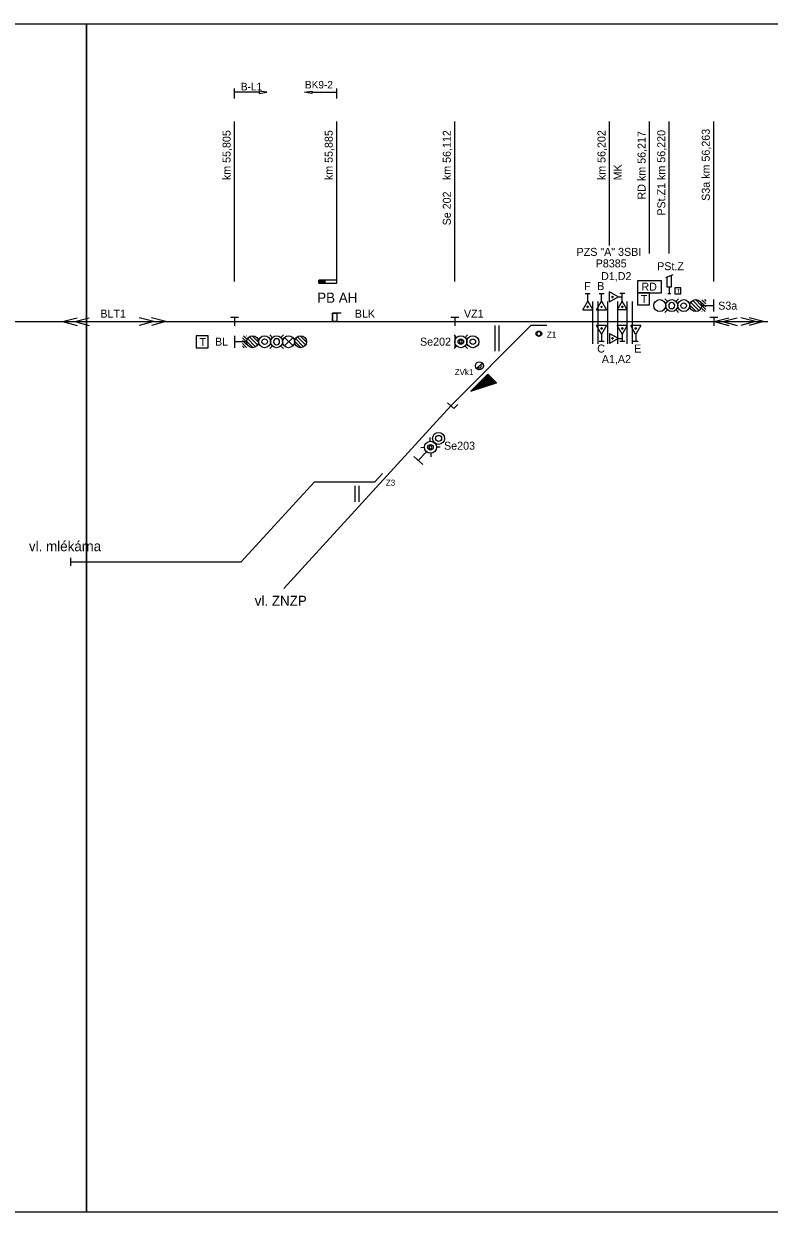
# Model space of a CAD drawing. Extents: x -1146 to 534, y 4 to 301.
# Drawn here: x -951.7 to -765.5, y 4.4 to 301.4 of the extents above; entities that cross this region are included whole.
import ezdxf

# ---------------------------------------------------------------- set-up
doc = ezdxf.new("R2010")
doc.units = 0
for name, color, linetype in [('_Nové', 7, 'Continuous'), ('formát tisku', 7, 'Continuous'), ('koleje', 7, 'Continuous'), ('návěstidla', 7, 'Continuous'), ('popisy', 7, 'Continuous'), ('čd', 7, 'Continuous')]:
    doc.layers.add(name, color=color, linetype=linetype)

# ---------------------------------------------------------------- blocks, each defined once
blk = doc.blocks.new('_X11')
for p, q in [((-0.5, 5.16), (0.34, 6)), ((-0.5, 5.33), (0.17, 6)), ((-0.5, 5.51), (-0.01, 6)), ((-0.5, 5.69), (-0.19, 6)), ((-0.5, 5.86), (-0.36, 6)), ((-0.5, 4.98), (0.5, 5.98)), ((-0.5, 4.8), (0.5, 5.8)), ((-0.5, 4.63), (0.5, 5.63)), ((-0.5, 4.45), (0.5, 5.45)), ((-0.5, 4.27), (0.5, 5.27)), ((-0.5, 4.1), (0.5, 5.1)), ((-0.42, 4), (0.5, 4.92)), ((-0.24, 4), (0.5, 4.74)), ((-0.07, 4), (0.5, 4.57)), ((0.11, 4), (0.5, 4.39)), ((0.29, 4), (0.5, 4.21)), ((0.46, 4), (0.5, 4.04))]:
    blk.add_line(p, q)
blk = doc.blocks.new('PZ15')
for p, q in [((0.5, 6), (-0.5, 6)), ((-0.5, 6), (-0.5, 0)), ((0.5, 0), (0.5, 6)), ((-0.5, 0), (0.5, 0))]:
    blk.add_line(p, q)
blk.add_lwpolyline([(0.5, 6), (0.5, 4), (-0.5, 4), (-0.5, 6)], close=True)
blk.add_lwpolyline([(-0.5, 6), (0.5, 6), (0.5, 4), (-0.5, 4), (-0.5, 6)])
blk.add_blockref('_X11', (0, 0))
blk = doc.blocks.new('O9')
for p, q in [((-1.5, 3), (-1.5, 0)), ((1.5, 3), (-1.5, 3)), ((1.5, 0), (1.5, 3)), ((-1.5, 0), (1.5, 0))]:
    blk.add_line(p, q)
blk.add_text('T', height=2).set_placement((-0.68, 0.41))
blk = doc.blocks.new('SB1')
for p, q in [((0, 1.08), (-1, 1.08)), ((1, 1.08), (0, 1.08)), ((0, 1.08), (0, -1.08))]:
    blk.add_line(p, q)
blk = doc.blocks.new('NS16')
for p, q in [((-1.499, 0.6437), (-1.1298, 1.0129)), ((-1.4356, 0), (-0.4227, 1.0129)), ((-0.7285, 0), (0.2844, 1.0129)), ((-0.0214, 0), (0.9915, 1.0129)), ((0.6857, 0), (1.499, 0.8133)), ((1.3928, 0), (1.499, 0.1062))]:
    blk.add_line(p, q)
blk = doc.blocks.new('NS14')
for p, q in [((0.1, 18), (-1.5, 16.4)), ((0.8, 17.7), (-1.2, 15.7)), ((1.3, 17.25), (-0.8, 15.2)), ((1.5, 16.6), (-0.1, 15)), ((-1, 11.5), (-1.7, 12.2)), ((1, 11.5), (1.7, 12.2)), ((-1, 9.5), (-1.7, 8.8)), ((1, 9.5), (1.7, 8.8)), ((0.1, 6), (-1.5, 4.4)), ((0.8, 5.7), (-1.2, 3.7)), ((1.3, 5.25), (-0.8, 3.2)), ((1.5, 4.6), (-0.1, 3)), ((0, 3), (0, 0)), ((-1.5, 0), (1.5, 0))]:
    blk.add_line(p, q)
for centre, radius in [((0, 16.5), 1.5), ((0, 13.5), 1.5), ((0, 7.5), 1.5), ((0, 4.5), 1.5), ((0, 7.5), 0.7)]:
    blk.add_circle(centre, radius)
for start, end in [(0, 180), (180, 0)]:
    blk.add_arc((0, 10.5), 0.75, start, end)
blk = doc.blocks.new('NS5')
for p, q in [((-1, 5.5), (-1.7, 6.2)), ((1, 5.5), (1.7, 6.2)), ((-1, 3.5), (-1.7, 2.8)), ((0, 3), (0, 0)), ((1, 3.5), (1.7, 2.8)), ((-1.5, 0), (1.5, 0))]:
    blk.add_line(p, q)
for centre, radius in [((0, 7.5), 1.5), ((0, 4.5), 1.5), ((0, 7.5), 0.75), ((0, 4.5), 0.7)]:
    blk.add_circle(centre, radius)
for start, end in [(0, 180), (180, 0)]:
    blk.add_arc((0, 4.5), 0.375, start, end)
blk = doc.blocks.new('NS1')
for p, q in [((-1, 2.5), (-1.7, 3.2)), ((1, 2.5), (1.7, 3.2)), ((-1, 0.5), (-1.7, -0.2)), ((-1.5, 0), (1.5, 0)), ((1, 0.5), (1.7, -0.2))]:
    blk.add_line(p, q)
for centre, radius in [((0, 4.5), 1.5), ((0, 1.5), 1.5), ((0, 4.5), 0.7)]:
    blk.add_circle(centre, radius)
for start, end in [(0, 180), (180, 0)]:
    blk.add_arc((0, 1.5), 0.375, start, end)
blk = doc.blocks.new('PZ2')
for start, end in [(0, 180), (180, 0)]:
    blk.add_arc((0, 2), 0.5, start, end)
blk = doc.blocks.new('SB4')
for q in [(-1.39, 1.08), (0, -1.08)]:
    blk.add_line((0, 1.08), q)
blk = doc.blocks.new('_X28')
for p, q in [((-3, 2.89), (-2.93, 2.96)), ((-3, 2.71), (-2.81, 2.9)), ((-3, 2.54), (-2.69, 2.85)), ((-3, 2.36), (-2.57, 2.79)), ((-3, 2.18), (-2.45, 2.73)), ((-3, 2.01), (-2.34, 2.67)), ((-3, 1.83), (-2.22, 2.61)), ((-3, 1.65), (-2.1, 2.55)), ((-3, 1.47), (-1.98, 2.49)), ((-3, 1.3), (-1.87, 2.43)), ((-3, 1.12), (-1.75, 2.37)), ((-3, 0.94), (-1.63, 2.31)), ((-3, 0.77), (-1.51, 2.26)), ((-3, 0.59), (-1.39, 2.2)), ((-3, 0.41), (-1.28, 2.14)), ((-3, 0.24), (-1.16, 2.08)), ((-3, 0.06), (-1.04, 2.02)), ((-2.88, 0), (-0.92, 1.96)), ((-2.71, 0), (-0.8, 1.9)), ((-2.53, 0), (-0.69, 1.84)), ((-2.35, 0), (-0.57, 1.78)), ((-2.18, 0), (-0.45, 1.73)), ((-2, 0), (-0.33, 1.67)), ((-1.82, 0), (-0.22, 1.61)), ((-1.65, 0), (-0.1, 1.55)), ((-1.47, 0), (0.02, 1.49)), ((-1.29, 0), (0.14, 1.43)), ((-1.12, 0), (0.26, 1.37)), ((-0.94, 0), (0.37, 1.31)), ((-0.76, 0), (0.49, 1.25)), ((-0.59, 0), (0.61, 1.2)), ((-0.41, 0), (0.73, 1.14)), ((-0.23, 0), (0.85, 1.08)), ((-0.06, 0), (0.96, 1.02)), ((0.12, 0), (1.08, 0.96)), ((0.3, 0), (1.2, 0.9)), ((0.47, 0), (1.32, 0.84)), ((0.65, 0), (1.43, 0.78)), ((0.83, 0), (1.55, 0.72)), ((1.01, 0), (1.67, 0.66)), ((1.18, 0), (1.79, 0.61)), ((1.36, 0), (1.91, 0.55)), ((1.54, 0), (2.02, 0.49)), ((1.71, 0), (2.14, 0.43)), ((1.89, 0), (2.26, 0.37)), ((2.07, 0), (2.38, 0.31)), ((2.24, 0), (2.5, 0.25)), ((2.42, 0), (2.61, 0.19)), ((2.6, 0), (2.73, 0.13)), ((2.77, 0), (2.85, 0.08)), ((2.95, 0), (2.97, 0.02))]:
    blk.add_line(p, q)
blk = doc.blocks.new('VU1')
blk.add_lwpolyline([(0, 1), (6, 1), (0, 4)], close=True)
blk.add_lwpolyline([(0, 4), (6, 1), (0, 1), (0, 4)])
blk.add_blockref('_X28', (3, 1))
blk = doc.blocks.new('PZ5')
blk.add_circle((0, 2), 1)
blk.add_arc((-0.01, 2), 0.5, 180, 0)
blk = doc.blocks.new('P1')
for p, q in [((-0.02, 3.02), (-2, 6.5)), ((2, 6.5), (-2, 6.5)), ((2, 6.5), (0.02, 3.02)), ((1, 0), (-1, 0)), ((0, 3), (0, 0))]:
    blk.add_line(p, q)
for start, end in [(90, 270), (270, 90)]:
    blk.add_arc((0.02, 5.27), 0.25, start, end)
blk = doc.blocks.new('P5')
for p, q in [((2, 6.5), (-2, 6.5)), ((-0.02, 3.02), (-2, 6.5)), ((2, 6.5), (0.02, 3.02)), ((-5.1, 3.3), (-1.62, 1.32)), ((-5.1, 3.3), (-5.1, -0.7)), ((-1.62, 1.28), (-5.1, -0.7)), ((-1.6, 1.3), (0, 1.3)), ((1, 0), (-1, 0)), ((0, 3), (0, 0))]:
    blk.add_line(p, q)
for centre, start, end in [((0.02, 5.27), 90, 270), ((0.02, 5.27), 270, 90), ((-3.87, 1.32), 0, 180), ((-3.87, 1.32), 180, 0)]:
    blk.add_arc(centre, 0.25, start, end)
blk = doc.blocks.new('NS12')
for p, q in [((-1, 11.5), (-1.7, 12.2)), ((1, 11.5), (1.7, 12.2)), ((-1, 9.5), (-1.7, 8.8)), ((1, 9.5), (1.7, 8.8)), ((0.1, 6), (-1.5, 4.4)), ((0.8, 5.7), (-1.2, 3.7)), ((1.3, 5.25), (-0.8, 3.2)), ((1.5, 4.6), (-0.1, 3)), ((0, 3), (0, 0)), ((-1.5, 0), (1.5, 0))]:
    blk.add_line(p, q)
for centre, radius in [((0, 13.5), 1.5), ((0, 7.5), 1.5), ((0, 4.5), 1.5), ((0, 7.5), 0.7)]:
    blk.add_circle(centre, radius)
for start, end in [(0, 180), (180, 0)]:
    blk.add_arc((0, 10.5), 0.75, start, end)
blk = doc.blocks.new('O8')
for p, q in [((1.25, 6.25), (-1.25, 5.25)), ((-0.75, 5.45), (-0.75, 2.25)), ((0.75, 2.25), (0.75, 6.05)), ((-0.75, 2.25), (0.75, 2.25)), ((-0.5, 0), (0.5, 0)), ((0, 2.25), (0, 0))]:
    blk.add_line(p, q)
blk = doc.blocks.new('SB11b')
for p, q in [((-1.5, 0), (1.5, 0)), ((1.5, 0), (1.5, -3))]:
    blk.add_line(p, q)
blk.add_lwpolyline([(1.5, 0), (0, 0), (0, -0.375), (0, -3), (1.5, -3)], close=True)
blk = doc.blocks.new('O10')
for p, q in [((3, 3), (-3, 3)), ((-3, 3), (-3, 0)), ((3, 0), (3, 3)), ((-3, 0), (3, 0))]:
    blk.add_line(p, q)
blk.add_text('RD', height=2).set_placement((-2.05, 0.5))

msp = doc.modelspace()

# ---------------------------------------------------------------- linework, layer by layer
for p, q in [((-935.96, 301.44), (-935.96, 292.56)), ((-805.36, 246), (-805.36, 277)), ((-795.35, 244), (-795.35, 277)), ((-790.43, 244), (-790.43, 277)), ((-779.32, 237), (-779.32, 277)), ((-809.65, 232), (-809.65, 221.46)), ((-808.28, 232), (-808.28, 221.46)), ((-805.78, 221.46), (-805.78, 232)), ((-803.21, 233.2), (-805.38, 234.44)), ((-805.38, 231.94), (-805.38, 234.44)), ((-805.38, 231.94), (-803.21, 233.18)), ((-802.21, 232.11), (-803.44, 229.94)), ((-803.36, 232), (-803.36, 221.46)), ((-803.19, 233.19), (-802.19, 233.19)), ((-801.57, 234), (-802.82, 234)), ((-802.19, 232.12), (-802.19, 234)), ((-800.94, 229.94), (-802.18, 232.11)), ((-801.07, 232), (-801.07, 221.46)), ((-799.7, 232), (-799.7, 221.46)), ((-800.94, 229.94), (-803.44, 229.94)), ((-941.98, 227), (-938.34, 227.95)), ((-941.98, 227), (-938.34, 226.05)), ((-938.94, 227), (-935.31, 227.95)), ((-938.94, 227), (-935.31, 226.05)), ((-919.19, 227), (-922.82, 227.95)), ((-919.19, 227), (-922.82, 226.05)), ((-916.15, 227), (-919.79, 227.95)), ((-916.15, 227), (-919.79, 226.05)), ((-779.23, 227), (-775.6, 227.95)), ((-779.23, 227), (-775.6, 226.05)), ((-777.13, 227), (-773.5, 227.95)), ((-777.13, 227), (-773.5, 226.05)), ((-768.93, 227), (-772.57, 227.95)), ((-768.93, 227), (-772.57, 226.05)), ((-766.88, 227), (-770.51, 227.95)), ((-766.88, 227), (-770.51, 226.05)), ((-935.96, 4.44), (-935.96, 13.33))]:
    msp.add_line(p, q)
for centre, radius in [((-804.61, 233.18), 0.156), ((-789.82, 231), 1.5), ((-810.8, 230.71), 0.156), ((-807.36, 230.71), 0.156), ((-802.18, 230.71), 0.156), ((-888.5, 222), 1.5), ((-823, 224), 0.7), ((-807.34, 225.31), 0.156), ((-804.61, 222.84), 0.156), ((-802.18, 225.31), 0.156), ((-798.81, 225.31), 0.156), ((-842.5, 222), 0.7), ((-850.08, 195.61), 0.7)]:
    msp.add_circle(centre, radius)
for centre, start, end in [((-804.61, 233.18), 0, 180), ((-804.61, 233.18), 180, 0), ((-802.18, 230.71), 0, 180), ((-802.18, 230.71), 180, 0)]:
    msp.add_arc(centre, 0.156, start, end)
at = {"layer": '_Nové'}
for p, q in [((-873.5, 282.8), (-873.5, 285.27)), ((-879.67, 284.33), (-873.42, 284.33))]:
    msp.add_line(p, q, dxfattribs=at)
msp.add_lwpolyline([(-879.67, 284.64), (-879.67, 284.02), (-881.55, 284.33)], close=True, dxfattribs=at)
at = {"layer": 'formát tisku'}
for points in [[(-1145.96, 301.44), (-935.96, 301.44), (-935.96, 4.44), (-1145.96, 4.44)], [(-935.96, 301.44), (-725.96, 301.44), (-725.96, 4.44), (-935.96, 4.44)]]:
    msp.add_lwpolyline(points, close=True, dxfattribs=at)
at = {"layer": 'koleje'}
for p, q in [((-961, 227), (-765.85, 227)), ((-845, 206), (-825, 226)), ((-834, 226), (-834, 219.63)), ((-833, 226), (-833, 219.63)), ((-821, 226), (-825, 226)), ((-886.69, 160.32), (-845, 206)), ((-864, 187), (-862.1, 189.09)), ((-897.34, 167), (-879.02, 186.98)), ((-879.02, 186.98), (-864, 187)), ((-869, 186), (-869, 182)), ((-868, 186), (-868, 182)), ((-940, 168), (-940, 166)), ((-940, 167), (-897.34, 167))]:
    msp.add_line(p, q, dxfattribs=at)
at = {"layer": 'návěstidla'}
for p, q in [((-886.53, 223.08), (-884.41, 220.96)), ((-886.53, 220.96), (-884.41, 223.08))]:
    msp.add_line(p, q, dxfattribs=at)
at = {"layer": 'popisy'}
for p, q in [((-899, 282.8), (-899, 285.27)), ((-892.84, 284.33), (-899.09, 284.33)), ((-899, 237), (-899, 277)), ((-873.5, 237), (-873.5, 277)), ((-844, 237), (-844, 277))]:
    msp.add_line(p, q, dxfattribs=at)
msp.add_lwpolyline([(-892.84, 284.64), (-892.84, 284.02), (-890.97, 284.33)], close=True, dxfattribs=at)
at = {"layer": 'čd'}
msp.add_lwpolyline([(-838.57, 215.26), (-837.51, 216.31), (-837.16, 216.67)], dxfattribs=at)
msp.add_lwpolyline([(-838.57, 215.26), (-837.16, 216.67), (-836.96, 216.4), (-836.88, 216.14), (-836.88, 215.78), (-836.99, 215.48), (-837.22, 215.2), (-837.56, 215.01), (-837.98, 214.97), (-838.17, 215.01)], close=True, dxfattribs=at)

# ---------------------------------------------------------------- block references
for name, p, xscale, yscale in [('O8', (-790.46, 234), 0.7499999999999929, 0.7499999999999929), ('O9', (-788.27, 233.99), 0.5000000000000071, 0.5000000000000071), ('P1', (-807.35, 222.01), 0.625, 0.625), ('P5', (-802.19, 222.01), 0.625, 0.625), ('P1', (-798.82, 222.01), 0.625, 0.625)]:
    msp.add_blockref(name, p, dxfattribs=dict(xscale=xscale, yscale=yscale))
at = {"xscale": 0.625, "yscale": 0.625, "rotation": 180}
for p in [(-810.79, 234), (-807.35, 234)]:
    msp.add_blockref('P1', p, dxfattribs=at)
for name, p, rotation in [('NS12', (-779.32, 231), 90), ('NS16', (-782.32, 231), -90.00000000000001)]:
    msp.add_blockref(name, p, dxfattribs=dict(rotation=rotation))
msp.add_blockref('SB1', (-779.32, 227))
at = {"layer": '_Nové', "xscale": 0.72, "yscale": -0.72, "rotation": 180}
msp.add_blockref('SB11b', (-873.5, 229.16), dxfattribs=at)
at = {"layer": 'návěstidla'}
for name, p, rotation in [('NS14', (-899, 222), -90.00000000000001), ('NS16', (-896, 222), 90), ('NS1', (-844, 222), -90.00000000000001), ('NS5', (-853.11, 192.29), -42.383604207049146)]:
    msp.add_blockref(name, p, dxfattribs=dict(at, rotation=rotation))
at = {"layer": 'čd', "xscale": 0.7500000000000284, "yscale": 0.7500000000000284, "rotation": 90}
msp.add_blockref('PZ15', (-873.5, 237), dxfattribs=at)
at = {"layer": 'čd'}
for name, p in [('O10', (-795.35, 234.24)), ('O9', (-796.85, 231.24)), ('SB1', (-899, 227)), ('SB1', (-844, 227)), ('O9', (-907.09, 220.5))]:
    msp.add_blockref(name, p, dxfattribs=at)
for name, p, rotation in [('PZ2', (-823, 226), 180), ('PZ5', (-836.45, 214.55), 45.000000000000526), ('VU1', (-836.45, 214.55), -135.00000000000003), ('SB4', (-845, 206), -132.38360420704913)]:
    msp.add_blockref(name, p, dxfattribs=dict(at, rotation=rotation))

# ---------------------------------------------------------------- texts
for s, height, p in [('B-L1', 1.875, (-897.43, 284.81)), ('PZS "A" 3SBI', 2, (-813.59, 243.44)), ('P8385', 2, (-808.81, 240.56)), ('PSt.Z', 2, (-793.47, 239.86)), ('D1,D2', 2, (-807.47, 237.38)), ('F', 2, (-811.71, 234.9)), ('B', 2, (-808.44, 234.9)), ('PB AH', 2.5, (-878.37, 231.74)), ('S3a', 2, (-778.21, 230)), ('Z1', 1.5, (-821, 223)), ('C', 2, (-808.44, 219.28)), ('E', 2, (-799.19, 219.28)), ('A1,A2', 2, (-807.29, 216.65))]:
    msp.add_text(s, height=height).set_placement(p)
for s, p in [('km 56,202', (-806.36, 262.37)), ('RD km 56,217', (-796.35, 257.53)), ('PSt.Z1 km 56,220', (-791.43, 253.5)), ('S3a km 56,263', (-780.32, 257.2)), ('MK', (-802.33, 262.32))]:
    msp.add_text(s, height=2, rotation=90).set_placement(p)
at = {"layer": '_Nové'}
msp.add_text('BK9-2', height=1.875, dxfattribs=at).set_placement((-881.42, 285.28))
at = {"layer": 'popisy'}
for s, p in [('km 55,805', (-900, 262.37)), ('km 55,885', (-874.5, 262.37)), ('km 56,112', (-845, 262.37)), ('Se 202', (-845, 251.06))]:
    msp.add_text(s, height=2, rotation=90, dxfattribs=at).set_placement(p)
for s, height, p in [('BLT1', 2, (-932.53, 228)), ('BLK', 2, (-868.97, 228)), ('VZ1', 2, (-841.71, 228)), ('BL', 2, (-903.89, 221)), ('Se202', 2, (-852.69, 221)), ('ZVk1', 1.5, (-844.03, 213.64)), ('Se203', 2, (-846.69, 195)), ('Z3', 1.5, (-861.23, 186)), ('vl. mlékárna', 2.5, (-950.36, 169.64)), ('vl. ZNZP', 2.5, (-893.97, 156))]:
    msp.add_text(s, height=height, dxfattribs=at).set_placement(p)

doc.saveas('drawing.dxf')
